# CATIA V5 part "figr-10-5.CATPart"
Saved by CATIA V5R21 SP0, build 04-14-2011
Part number: Part1
Bounding box of the stored display mesh (mm): x -9.888 to 10, y -9.972 to 9.972, z 0 to 10
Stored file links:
  D:\CATIA V5R21 E-RESOURCES\CATIA-V5R21\catia-v5r21-prt\c10-catia-v5r20-prt\c10-catia-v5r21-figr-10-5.CATPart
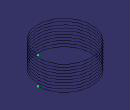
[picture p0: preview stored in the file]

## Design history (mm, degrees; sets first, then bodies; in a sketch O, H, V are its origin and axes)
Set1
  Helix1: Direction {line stored without definition}, RefPoint {point type Coord, X 10, Y 0, Z 0}, Pitch 1, Height 10, TaperAngle 0
Body1 (main body)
